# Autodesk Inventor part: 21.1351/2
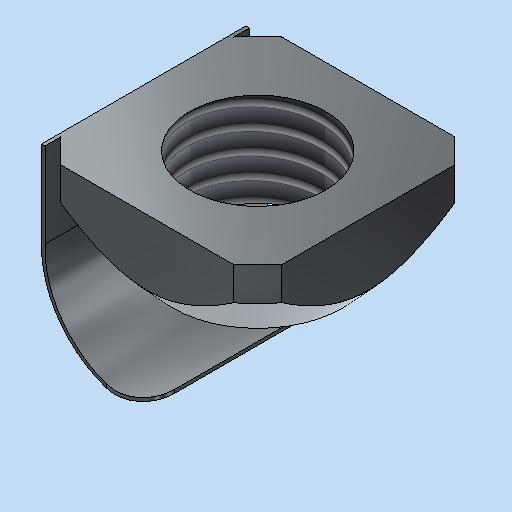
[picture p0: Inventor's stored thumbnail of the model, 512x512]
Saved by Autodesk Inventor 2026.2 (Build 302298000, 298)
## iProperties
Created: 2006-12
Part Number: 21.1351/2
Document SubType Name: Modeling
Designer: Andy Moles
Material: Steel, Mild
Density: 7.85 g/cm^3
Mass: 4.24899 g
Surface Area: 8.34272 cm^2
Volume: 0.541273 cm^3
Description: M8 SQUARE NUT POS FXG
Vendor: S
Appearance: Zinc
Title: M8 SQUARE NUT POS FXG
Author: Andy Moles
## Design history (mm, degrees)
sketch "Sketch2"
  geometry: L1 (-5.086, -6.5)-(5.086, -6.5); L2 (6.5, -5.086)-(6.5, 5.086); L3 (5.086, 6.5)-(-5.086, 6.5); L4 (-6.5, 5.086)-(-6.5, -5.086); L5 (-6.5, 6.5)-(6.5, -6.5); L6 (5.086, 6.5)-(6.5, 5.086); L7 (0, -6.5)-(0, 6.5); L8 (-6.5, 0)-(6.5, 0); L9 (-5.086, 6.5)-(-6.5, 5.086); L10 (-5.086, -6.5)-(-6.5, -5.086); L11 (5.086, -6.5)-(6.5, -5.086); C1 r 4 at (0, 0); 2 further points
  constraints: 22 end point, 6 symmetric about line, 4 parallel, 3 midpoint, 2 coincident, 2 perpendicular, 1 centre point, 1 horizontal
  dimensions: "THREAD" = 8 diameter of C1; "d3" = 45 deg angle of L3 L6 (derived); "d4" = 2 distance of L3.start L2.end
extrude "Extrusion1" new body sketch "Sketch2" distance "d5" = 5.5; taper "d6" = 0 deg
workplane "Work Plane1"
sketch "Sketch4"
  geometry: L1 (12.192, 0)-(4.192, 0) reference; L2 (8.192, 0)-(13.192, 0); L3 (16.385, 5.5)-(16.385, 3.5); L4 (13.192, 0)-(16.797, 3.952); L5 (13.192, 0)-(16.385, 0); L6 (16.385, 3.5)-(16.385, 0); L7 (16.797, 3.952)-(16.797, -0.412); L8 (16.797, -0.412)-(13.192, -0.412); L9 (13.192, -0.412)-(13.192, 0); L10 (8.192, 5.5)-(8.192, 0); L11 (16.385, 5.5)-(16.385, 0) reference; L12 (16.385, 3.5)-(17.502, 3.5); L13 (9.192, 5.5)-(16.385, 5.5) reference
  constraints: 20 end point, 6 perpendicular, 1 collinear, 1 midpoint, 1 parallel, 1 point on line
  dimensions: "d10" = 5 distance of L2.start L2.end; "d15" = 2 distance between parallel lines of L12 L13
revolve "Revolution1" sketch "Sketch4" stored, may be unused: angle "d12" = 90 deg
thread "Thread1" dims "d13" = 10, "d14" = 0
sketch "Sketch6"
  geometry: L1 (2.954, -2.535)-(2.954, 6.006); L2 (2.954, -2.535)-(2.954, -7.535); L3 (2.954, -2.535)-(3.154, -2.535); L4 (3.154, -2.535)-(3.154, -7.535); L5 (-2.646, -13.135)-(-2.646, -13.335); L6 (2.954, 0)-(2.954, -1.933); L7 (-8.632, -2.535)-(1.539, -2.535) reference; L8 (2.954, -2.535)-(2.954, -4.468) reference; A1 r 5.374 centre (-2.416, -7.766) between (-2.646, -13.135) and (2.954, -7.535); A2 r 5.574 centre (-2.416, -7.766) between (-2.646, -13.335) and (3.154, -7.535); 4 further points; 1 other entity
  constraints: 12 end point, 4 point on circle, 3 collinear, 2 centre point, 2 horizontal, 2 parallel, 2 perpendicular, 1 coincident, 3 other
  dimensions: "d25" = 5 distance of L1.start L2.end; "d23" = 0.2 distance of L1.start L3.end; "d22" = 0.2 distance of L5.start L5.end; "d21" = 10.8 distance from line of L5.end L3; "d24" = 5.37434 radius of A1
extrude "Extrusion3" join sketch "Sketch6" taper "d27" = 0 deg; stored distance "d28" = 12
fillet "Fillet2" dims "d29" = 2
body "Solid1"
